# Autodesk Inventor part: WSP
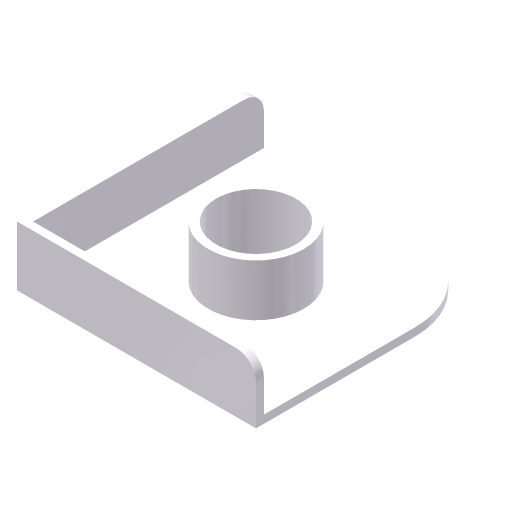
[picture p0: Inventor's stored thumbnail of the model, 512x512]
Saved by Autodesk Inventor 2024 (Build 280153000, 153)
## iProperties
Company: ATC
Shininess: 20.0
Length Units: 11269
Angle Units: 11279
Time Units: 11290
Mass Units: 11283
Length Display Precision: 3
Angle Display Precision: 2
Compacted: True
Created: 2023-03
Part Number: WSP
Document SubType Name: Modeling
Designer: Andrzej Jaskulski
Density: 1 g/cm^3
Material: Kurs-AJ
Appearance: Kurs-AJ
Checked By: A.J.
Engr Approved By: Andrzej Jaskulski
Mfg Approved By: Andrzej Jaskulski
Authority: A.J.
Density: 0.0
Volumn: 0.0
Area: 0.0
PropertySet Name: Model Information
Control State: 0
Master: False
Checked Out: False
Title: A.J.: Kurs R2024-MEP
Author: Andrzej Jaskulski
Revision Number: 1/24
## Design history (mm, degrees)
sketch "Sketch1"
  geometry: L1 (0, 0)-(60, 0); L2 (60, 0)-(60, 60); L3 (60, 60)-(0, 60); L4 (0, 60)-(0, 0)
  constraints: 8 end point, 2 parallel, 1 horizontal, 1 perpendicular, 1 other
  dimensions: "d0" = 60 distance of L1.start L1.end (= x); "d1" = 60 distance of L1.end L2.end (= y)
extrude "Baza" new body sketch "Sketch1" distance "d2" = 15 (= h); taper "d3" = 0 deg
sketch "Sketch3"
  geometry: L1 (0, 0)-(0, 60) reference; L2 (60, 0)-(0, 0) reference; 1 further point
  dimensions: "d9" = 30 distance from line of L1 point (30, 30) (= Lx); "d10" = 30 distance from line of L2 point (30, 30) (= Ly)
hole "Otwór" sketch "Sketch3" at (30, 30) diameter "d7" = 20 (= d); stored, may be unused: countersink angle "d18" = 60 deg, drill point angle "d20" = 118 deg; dims "d8" = 6, "d16" = 4, "d17" = 2, "d19" = 8
fillet "Zaokrąglenie1" dims "d4" = 20 (= d)
fillet "Zaokrąglenie2" dims "d5" = 5 (= 0.5 x r)
feature "Skorupa1" dims "d6" = 2
node "Bryła1"
node "Korpusy bryłowe"
node "Korpusy powierzchniowe"
other parameters: "inna_glob" = 19 [user parameter], "inna2_glob" = 21 [user parameter], "x" = 60 [user parameter; used in 1 equation term], "y" = 60 [user parameter; used in 1 equation term], "h" = 15 [user parameter; used in 1 equation term], "Lx" = 30 [user parameter; used in 1 equation term], "Ly" = 30 [user parameter; used in 1 equation term], "L2" = 1 [user parameter], "d" = 20 (= 2 x r) [user parameter; used in 2 equation terms], "wys_glob" = 15 [user parameter]
